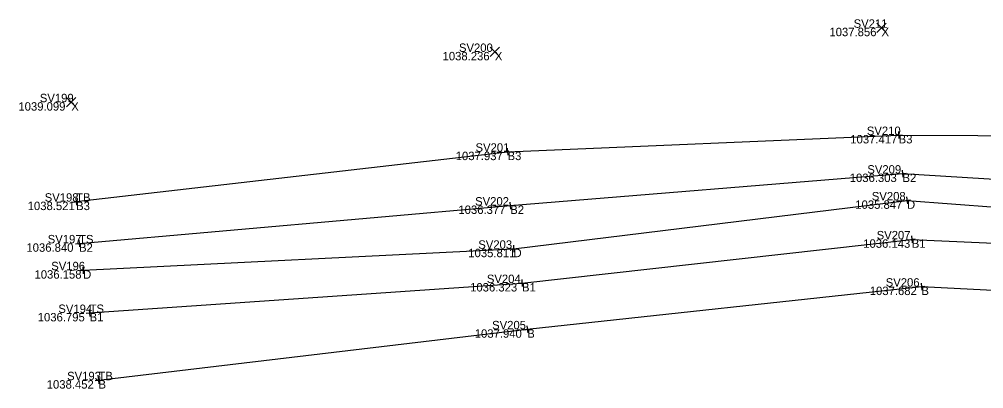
# Model space of a CAD drawing. Extents: x 1542529 to 1609210, y 587215 to 645373.
# Drawn here: x 1608653.7 to 1608791, y 645274.5 to 645327.2 of the extents above; entities that cross this region are included whole.
import ezdxf

# ---------------------------------------------------------------- set-up
doc = ezdxf.new("R2010")
doc.units = 0
for name, color, linetype in [('DR_X_Ditch', 7, 'Continuous'), ('SV_X_Random_Point', 7, 'Continuous'), ('SV_X_Shot_Marker', 7, 'Continuous'), ('SV_X_Text_Comment', 7, 'Continuous'), ('SV_X_Text_Description', 7, 'Continuous'), ('SV_X_Text_Elevation', 7, 'Continuous'), ('SV_X_Text_Name', 7, 'Continuous'), ('SV_X_Toe_of_Slope', 7, 'Continuous'), ('SV_X_Top_of_Bank', 7, 'Continuous')]:
    doc.layers.add(name, color=color, linetype=linetype)

msp = doc.modelspace()

# ---------------------------------------------------------------- linework, layer by layer
at = {"layer": 'DR_X_Ditch'}
msp.add_lwpolyline([(1608662.8, 645291.41), (1608724.04, 645294.47), (1608780.04, 645301.36), (1608836.85, 645297.07), (1608887.88, 645291.21), (1608917.04, 645295.13)], dxfattribs=at)
at = {"layer": 'SV_X_Random_Point'}
for p, q in [((1608775.75, 645325.29), (1608777.08, 645326.62)), ((1608775.75, 645326.62), (1608777.08, 645325.29)), ((1608720.72, 645321.85), (1608722.06, 645323.18)), ((1608720.72, 645323.18), (1608722.06, 645321.85)), ((1608660.45, 645314.68), (1608661.78, 645316.01)), ((1608660.45, 645316.01), (1608661.78, 645314.68))]:
    msp.add_line(p, q, dxfattribs=at)
at = {"layer": 'SV_X_Shot_Marker'}
for p, q in [((1608778.35, 645310.66), (1608779.35, 645310.7)), ((1608778.83, 645311.18), (1608778.87, 645310.18)), ((1608778.85, 645310.68), (1608778.85, 645310.68)), ((1608723.14, 645308.79), (1608723.25, 645307.8)), ((1608722.7, 645308.24), (1608723.69, 645308.35)), ((1608723.2, 645308.3), (1608723.2, 645308.3)), ((1608778.91, 645305.14), (1608779.9, 645305.22)), ((1608779.36, 645305.68), (1608779.44, 645304.68)), ((1608779.4, 645305.18), (1608779.4, 645305.18)), ((1608779.98, 645301.85), (1608780.11, 645300.86)), ((1608661.3, 645301.12), (1608662.3, 645301.24)), ((1608661.74, 645301.68), (1608661.86, 645300.68)), ((1608661.8, 645301.18), (1608661.8, 645301.18)), ((1608723.08, 645300.59), (1608724.08, 645300.67)), ((1608723.54, 645301.13), (1608723.63, 645300.13)), ((1608723.58, 645300.63), (1608723.58, 645300.63)), ((1608779.55, 645301.3), (1608780.54, 645301.42)), ((1608780.04, 645301.36), (1608780.04, 645301.36)), ((1608780.67, 645296.31), (1608780.78, 645295.32)), ((1608661.72, 645295.19), (1608662.72, 645295.28)), ((1608662.18, 645295.73), (1608662.27, 645294.74)), ((1608662.22, 645295.24), (1608662.22, 645295.24)), ((1608724.02, 645294.97), (1608724.07, 645293.97)), ((1608780.23, 645295.76), (1608781.22, 645295.87)), ((1608780.72, 645295.81), (1608780.72, 645295.81)), ((1608723.54, 645294.44), (1608724.54, 645294.49)), ((1608724.04, 645294.47), (1608724.04, 645294.47)), ((1608662.3, 645291.38), (1608663.3, 645291.43)), ((1608662.77, 645291.91), (1608662.82, 645290.91)), ((1608662.8, 645291.41), (1608662.8, 645291.41)), ((1608724.75, 645289.55), (1608725.75, 645289.61)), ((1608725.22, 645290.08), (1608725.29, 645289.08)), ((1608725.25, 645289.58), (1608725.25, 645289.58)), ((1608782.04, 645289.57), (1608782.15, 645288.58)), ((1608781.6, 645289.02), (1608782.59, 645289.13)), ((1608782.09, 645289.07), (1608782.09, 645289.07)), ((1608663.22, 645285.29), (1608664.21, 645285.36)), ((1608663.68, 645285.82), (1608663.75, 645284.82)), ((1608663.72, 645285.32), (1608663.72, 645285.32)), ((1608725.51, 645282.93), (1608726.5, 645283.05)), ((1608725.94, 645283.49), (1608726.06, 645282.49)), ((1608726, 645282.99), (1608726, 645282.99)), ((1608664.49, 645275.68), (1608665.48, 645275.8)), ((1608664.92, 645276.24), (1608665.04, 645275.24)), ((1608664.98, 645275.74), (1608664.98, 645275.74))]:
    msp.add_line(p, q, dxfattribs=at)
at = {"layer": 'SV_X_Toe_of_Slope'}
for points in [[(1608662.22, 645295.24), (1608723.58, 645300.63), (1608779.4, 645305.18), (1608836.47, 645301.69), (1608887.58, 645294.65), (1608917.25, 645295.93)], [(1608663.72, 645285.32), (1608725.25, 645289.58), (1608780.72, 645295.81), (1608837.12, 645293.26), (1608888.1, 645288.34), (1608916.87, 645294.03)]]:
    msp.add_lwpolyline(points, dxfattribs=at)
at = {"layer": 'SV_X_Top_of_Bank'}
for points in [[(1608661.8, 645301.18), (1608723.2, 645308.3), (1608778.85, 645310.68), (1608835.37, 645310.41), (1608887.05, 645302.6), (1608917.78, 645297.25), (1608920.26, 645299.01), (1608924.89, 645324.56)], [(1608664.98, 645275.74), (1608726, 645282.99), (1608782.09, 645289.07), (1608838.61, 645286.21), (1608887.62, 645285.23), (1608916.73, 645292.44), (1608916.53, 645287.04), (1608906.14, 645278.79)]]:
    msp.add_lwpolyline(points, dxfattribs=at)

# ---------------------------------------------------------------- texts
at = {"layer": 'SV_X_Text_Comment'}
for s, p in [('X', (1608776.41, 645324.76)), ('X', (1608721.39, 645321.32)), ('X', (1608661.11, 645314.15)), ('B3', (1608778.85, 645309.48)), ('B3', (1608723.2, 645307.1)), ('B2', (1608779.4, 645303.98)), ('B3', (1608661.8, 645299.98)), ('B2', (1608723.58, 645299.43)), ('D', (1608780.04, 645300.16)), ('B2', (1608662.22, 645294.04)), ('B1', (1608780.72, 645294.61)), ('D', (1608724.04, 645293.27)), ('D', (1608662.8, 645290.21)), ('B1', (1608725.25, 645288.38)), ('B', (1608782.09, 645287.87)), ('B1', (1608663.72, 645284.12)), ('B', (1608726, 645281.79)), ('B', (1608664.98, 645274.54))]:
    msp.add_text(s, height=1.2, dxfattribs=at).set_placement(p)
at = {"layer": 'SV_X_Text_Description'}
for s, p in [('TB', (1608661.8, 645301.18)), ('TS', (1608662.22, 645295.24)), ('TS', (1608663.72, 645285.32)), ('TB', (1608664.98, 645275.74))]:
    msp.add_text(s, height=1.2, dxfattribs=at).set_placement(p)
at = {"layer": 'SV_X_Text_Elevation'}
for s, p in [('1037.856', (1608769, 645324.76)), ('1038.236', (1608713.95, 645321.32)), ('1039.099', (1608653.59, 645314.15)), ('1037.417', (1608771.97, 645309.48)), ('1037.937', (1608715.82, 645307.1)), ('1036.303', (1608771.89, 645303.98)), ('1038.521', (1608654.91, 645299.98)), ('1036.377', (1608716.2, 645299.43)), ('1035.847', (1608772.68, 645300.16)), ('1036.840', (1608654.73, 645294.04)), ('1036.143', (1608773.81, 645294.61)), ('1035.811', (1608717.61, 645293.27)), ('1036.158', (1608655.88, 645290.21)), ('1036.323', (1608717.87, 645288.38)), ('1037.682', (1608774.74, 645287.87)), ('1036.795', (1608656.34, 645284.12)), ('1037.940', (1608718.53, 645281.79)), ('1038.452', (1608657.62, 645274.54))]:
    msp.add_text(s, height=1.2, dxfattribs=at).set_placement(p)
at = {"layer": 'SV_X_Text_Name'}
for s, p in [('SV211', (1608772.44, 645325.96)), ('SV200', (1608716.28, 645322.52)), ('SV199', (1608656.64, 645315.35)), ('SV210', (1608774.32, 645310.68)), ('SV201', (1608718.64, 645308.3)), ('SV209', (1608774.39, 645305.18)), ('SV198', (1608657.33, 645301.18)), ('SV202', (1608718.58, 645300.63)), ('SV208', (1608775.03, 645301.36)), ('SV197', (1608657.76, 645295.24)), ('SV207', (1608775.72, 645295.81)), ('SV203', (1608719.03, 645294.47)), ('SV196', (1608658.26, 645291.41)), ('SV204', (1608720.25, 645289.58)), ('SV206', (1608777.01, 645289.07)), ('SV194', (1608659.27, 645285.32)), ('SV205', (1608721, 645282.99)), ('SV193', (1608660.52, 645275.74))]:
    msp.add_text(s, height=1.2, dxfattribs=at).set_placement(p)

doc.saveas('drawing.dxf')
